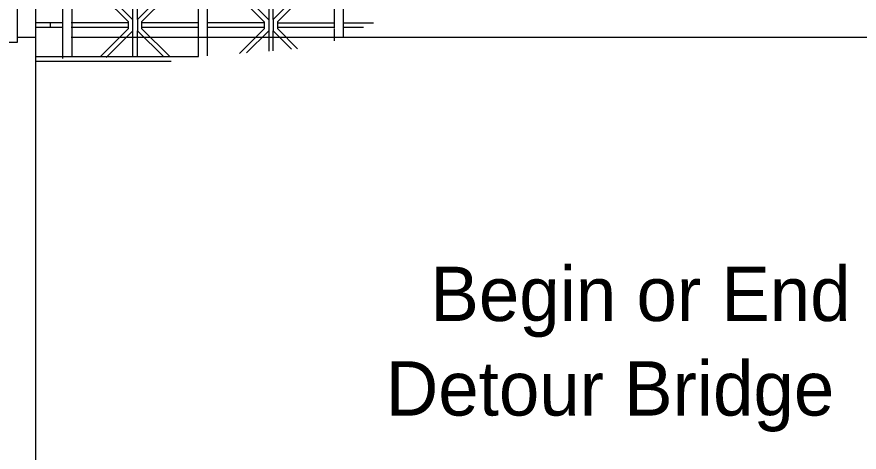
# Model space of a CAD drawing. Extents: x -58 to 62, y 0 to 81.
# Drawn here: x 18.684 to 22.558, y 25.727 to 27.73 of the extents above; entities that cross this region are included whole.
import ezdxf

# ---------------------------------------------------------------- set-up
doc = ezdxf.new("R2010")
doc.units = 0
for name, color, linetype in [('SteelMisc', 7, 'Continuous'), ('SteelMisc_h', 7, 'Continuous'), ('TextStructures', 7, 'Continuous'), ('Wood', 7, 'Continuous'), ('Wood_h', 7, 'Continuous')]:
    doc.layers.add(name, color=color, linetype=linetype)

msp = doc.modelspace()

# ---------------------------------------------------------------- linework, layer by layer
at = {"layer": 'SteelMisc'}
msp.add_line((18.7698, 30.2595), (18.7698, 3.773), dxfattribs=at)
msp.add_lwpolyline([(18.5719, 27.6137), (18.6866, 27.6137), (18.6866, 28.6554), (18.5719, 28.6554)], dxfattribs=at)
at = {"layer": 'SteelMisc_h'}
for p, q in [((19.2178, 27.5453), (19.2178, 30.2595)), ((19.2386, 27.7175), (19.2386, 30.2595)), ((19.8428, 30.2595), (19.8428, 27.5723)), ((19.8636, 27.717), (19.8636, 28.2895)), ((18.9365, 28.0284), (18.9365, 27.5467)), ((18.8949, 28.0038), (18.8949, 27.5382)), ((18.9357, 27.969), (19.197, 27.7077)), ((18.9573, 27.9769), (19.2178, 27.7164)), ((18.9611, 27.9731), (19.2178, 27.7164)), ((19.4992, 27.9781), (19.2386, 27.7175)), ((19.5197, 27.9691), (19.2594, 27.7088)), ((19.5199, 27.6791), (19.5199, 27.9797)), ((19.5615, 27.551), (19.5615, 27.9785)), ((19.5823, 27.9768), (19.8427, 27.7164)), ((20.1242, 27.9775), (19.8636, 27.717)), ((20.1449, 27.6786), (20.1449, 27.9792)), ((20.1865, 27.6386), (20.1865, 27.978)), ((19.5617, 27.968), (19.822, 27.7076)), ((20.1447, 27.9686), (19.8844, 27.7083)), ((19.8427, 27.7164), (19.7661, 27.793)), ((18.8952, 27.7016), (18.7698, 27.7016)), ((18.8376, 27.7016), (18.8376, 27.6809)), ((19.1946, 27.7016), (18.9347, 27.7016)), ((19.197, 27.7077), (19.197, 27.6748)), ((19.2386, 27.7175), (19.2386, 27.6662)), ((19.5179, 27.7016), (19.2586, 27.7016)), ((19.2594, 27.6748), (19.2594, 27.7088)), ((19.8207, 27.7016), (19.561, 27.7016)), ((19.822, 27.7076), (19.822, 27.6749)), ((19.8636, 27.717), (19.8636, 27.6657)), ((20.1429, 27.7011), (19.8836, 27.7011)), ((19.8844, 27.6743), (19.8844, 27.7083)), ((20.3251, 27.7011), (20.186, 27.7011)), ((18.8952, 27.6809), (18.7698, 27.6809)), ((19.1946, 27.6809), (18.9347, 27.6809)), ((19.0679, 27.5458), (19.197, 27.6748)), ((19.0951, 27.5434), (19.2178, 27.6661)), ((19.3581, 27.5467), (19.2386, 27.6662)), ((19.2386, 27.5453), (19.2386, 27.6662)), ((19.3872, 27.547), (19.2594, 27.6748)), ((19.5179, 27.6809), (19.2616, 27.6809)), ((19.5199, 27.5467), (19.5199, 27.6774)), ((19.8207, 27.6809), (19.5596, 27.6809)), ((19.7082, 27.5611), (19.822, 27.6749)), ((19.7404, 27.5638), (19.8428, 27.6662)), ((19.9482, 27.5811), (19.8636, 27.6657)), ((19.8636, 27.574), (19.8636, 27.6657)), ((19.9754, 27.5834), (19.8844, 27.6743)), ((20.1429, 27.6803), (19.8866, 27.6803)), ((20.1449, 27.6198), (20.1449, 27.6769)), ((20.2791, 27.6803), (20.1846, 27.6803)), ((19.5192, 27.5453), (18.7698, 27.5453)), ((19.3936, 27.5246), (18.7698, 27.5246))]:
    msp.add_line(p, q, dxfattribs=at)
at = {"layer": 'Wood'}
msp.add_line((18.7698, 27.6345), (18.6866, 27.6345), dxfattribs=at)
at = {"layer": 'Wood_h'}
msp.add_line((42.5747, 27.6345), (18.9335, 27.6345), dxfattribs=at)

# ---------------------------------------------------------------- texts
at = {"layer": 'TextStructures'}
for s, p in [('Begin or End', (20.5861, 26.3306)), ('Detour Bridge', (20.3811, 25.8956))]:
    msp.add_text(s, height=0.25, dxfattribs=at).set_placement(p)

doc.saveas('drawing.dxf')
